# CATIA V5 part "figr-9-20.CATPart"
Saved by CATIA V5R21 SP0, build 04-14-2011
Part number: Part3
Bounding box of the stored display mesh (mm): x -112 to 0, y -101.683 to 100, z -80.304 to 44.415
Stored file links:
  D:\CATIA V5R21 E-RESOURCES\CATIA-V5R21\catia-v5r21-prt\c09-catia-v5r20-prt\c09-catia-v5r21-figr-9-20.CATPart
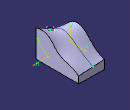
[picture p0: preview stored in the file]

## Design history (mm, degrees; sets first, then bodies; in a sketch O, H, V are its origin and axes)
Set1
  Plane1: type Offset, RefPlane yz-plane, Offset -112
  Plane2: type Offset, RefPlane yz-plane, Offset -63
  Plane3: type Normal, Curve Sketch4, RefPoint vertex of Sketch4
Body1 (main body)
  Sketch1 on yz-plane, origin (0, 0, 0), H (0, 1, 0), V (0, 0, 1)
    spline S1 through (-92.6897, 40.1119) (-30, 30) (10, -10) (60, -30) (97.3103, -50.3041)
    line L1 (97.3103, -50.3041) -> (97.3103, -80.3041)
    line L2 (97.3103, -80.3041) -> (-92.6897, -80.3041)
    line L3 (-92.6897, -80.3041) -> (-92.6897, 40.1119)
    point P3 (-92.6897, 40.1119)
    point P4 (97.3103, -50.3041)
    point P5 (-92.6897, 40.1119)
    point P6 (97.3103, -50.3041)
    vertical: L1 V, L3 V
    horizontal: L2 H
    coincidence: P5 P3, P6 P4
  Sketch2 on Plane1, origin (-112, 0, 0), H (0, 1, 0), V (0, 0, 1)
    spline S1 through (-90, -30) (-70, 10) (-20, 40) (40, 0) (100, -40)
    line L1 (100, -40) -> (100, -80)
    line L2 (100, -80) -> (-90, -80)
    line L3 (-90, -80) -> (-90, -30)
    point P3 (-90, -30)
    point P4 (100, -40)
    point P5 (40, 0)
    point P6 (-90, -30)
    point P7 (100, -40)
    coincidence: P5 H, P6 P3, P7 P4
    vertical: L1 V, L3 V
    horizontal: L2 H
  Loft1: Sections (Sketch1; Sketch2)
  Sketch3 on Plane3, origin (0, -40.1726, -44.9298), H (1, 0, 0), V (0, -0.7455, 0.6665)
    point P1 (-63, 68.4187)
    line L1 (-63, 68.4187) -> (-75.2117, 62.4925)
    line L2 (-75.2117, 62.4925) -> (-79.6266, 71.5898)
    line L3 (-79.6266, 71.5898) -> (-57.1205, 82.5119)
    line L4 (-57.1205, 82.5119) -> (-52.7056, 73.4145)
    point P5 (-52.7056, 73.4145)
    line L5 (-52.7056, 73.4145) -> (-63, 68.4187)
    reference projected point E1 (-63, 68.4187) from vertex of Sketch4
    perpendicularity: L2 L1
    parallelism: L3 L1, L4 L2, L5 L1
    coincidence: P5 L1, P1 E1
  Sketch4 on Plane2, origin (-63, 0, 0), H (0, 1, 0), V (0, 0, 1)
    intersected curve E1 from face of Loft1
